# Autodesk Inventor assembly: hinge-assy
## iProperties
Author: Administrator
Created: 2001-01
Part Number: hinge-assy
Document SubType Name: Assembly
Designer: Administrator
Control State: 0
Master: False
Checked Out: False
PropertySet Name: Design Tracking Control
Shininess: 0.0
PropertySet Name: _Private Model Information
Density: 0.0
Volumn: 0.0
Area: 0.0
PropertySet Name: Model Information
